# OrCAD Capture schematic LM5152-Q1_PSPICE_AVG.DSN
size Custom; title: LM5152-Q1 2.2-MHz Wide VIN Low-IQ Synchronous; rev: 1.0; note: Datasheet: NA     EVM: NA; note: Synchronous Step Down Converter
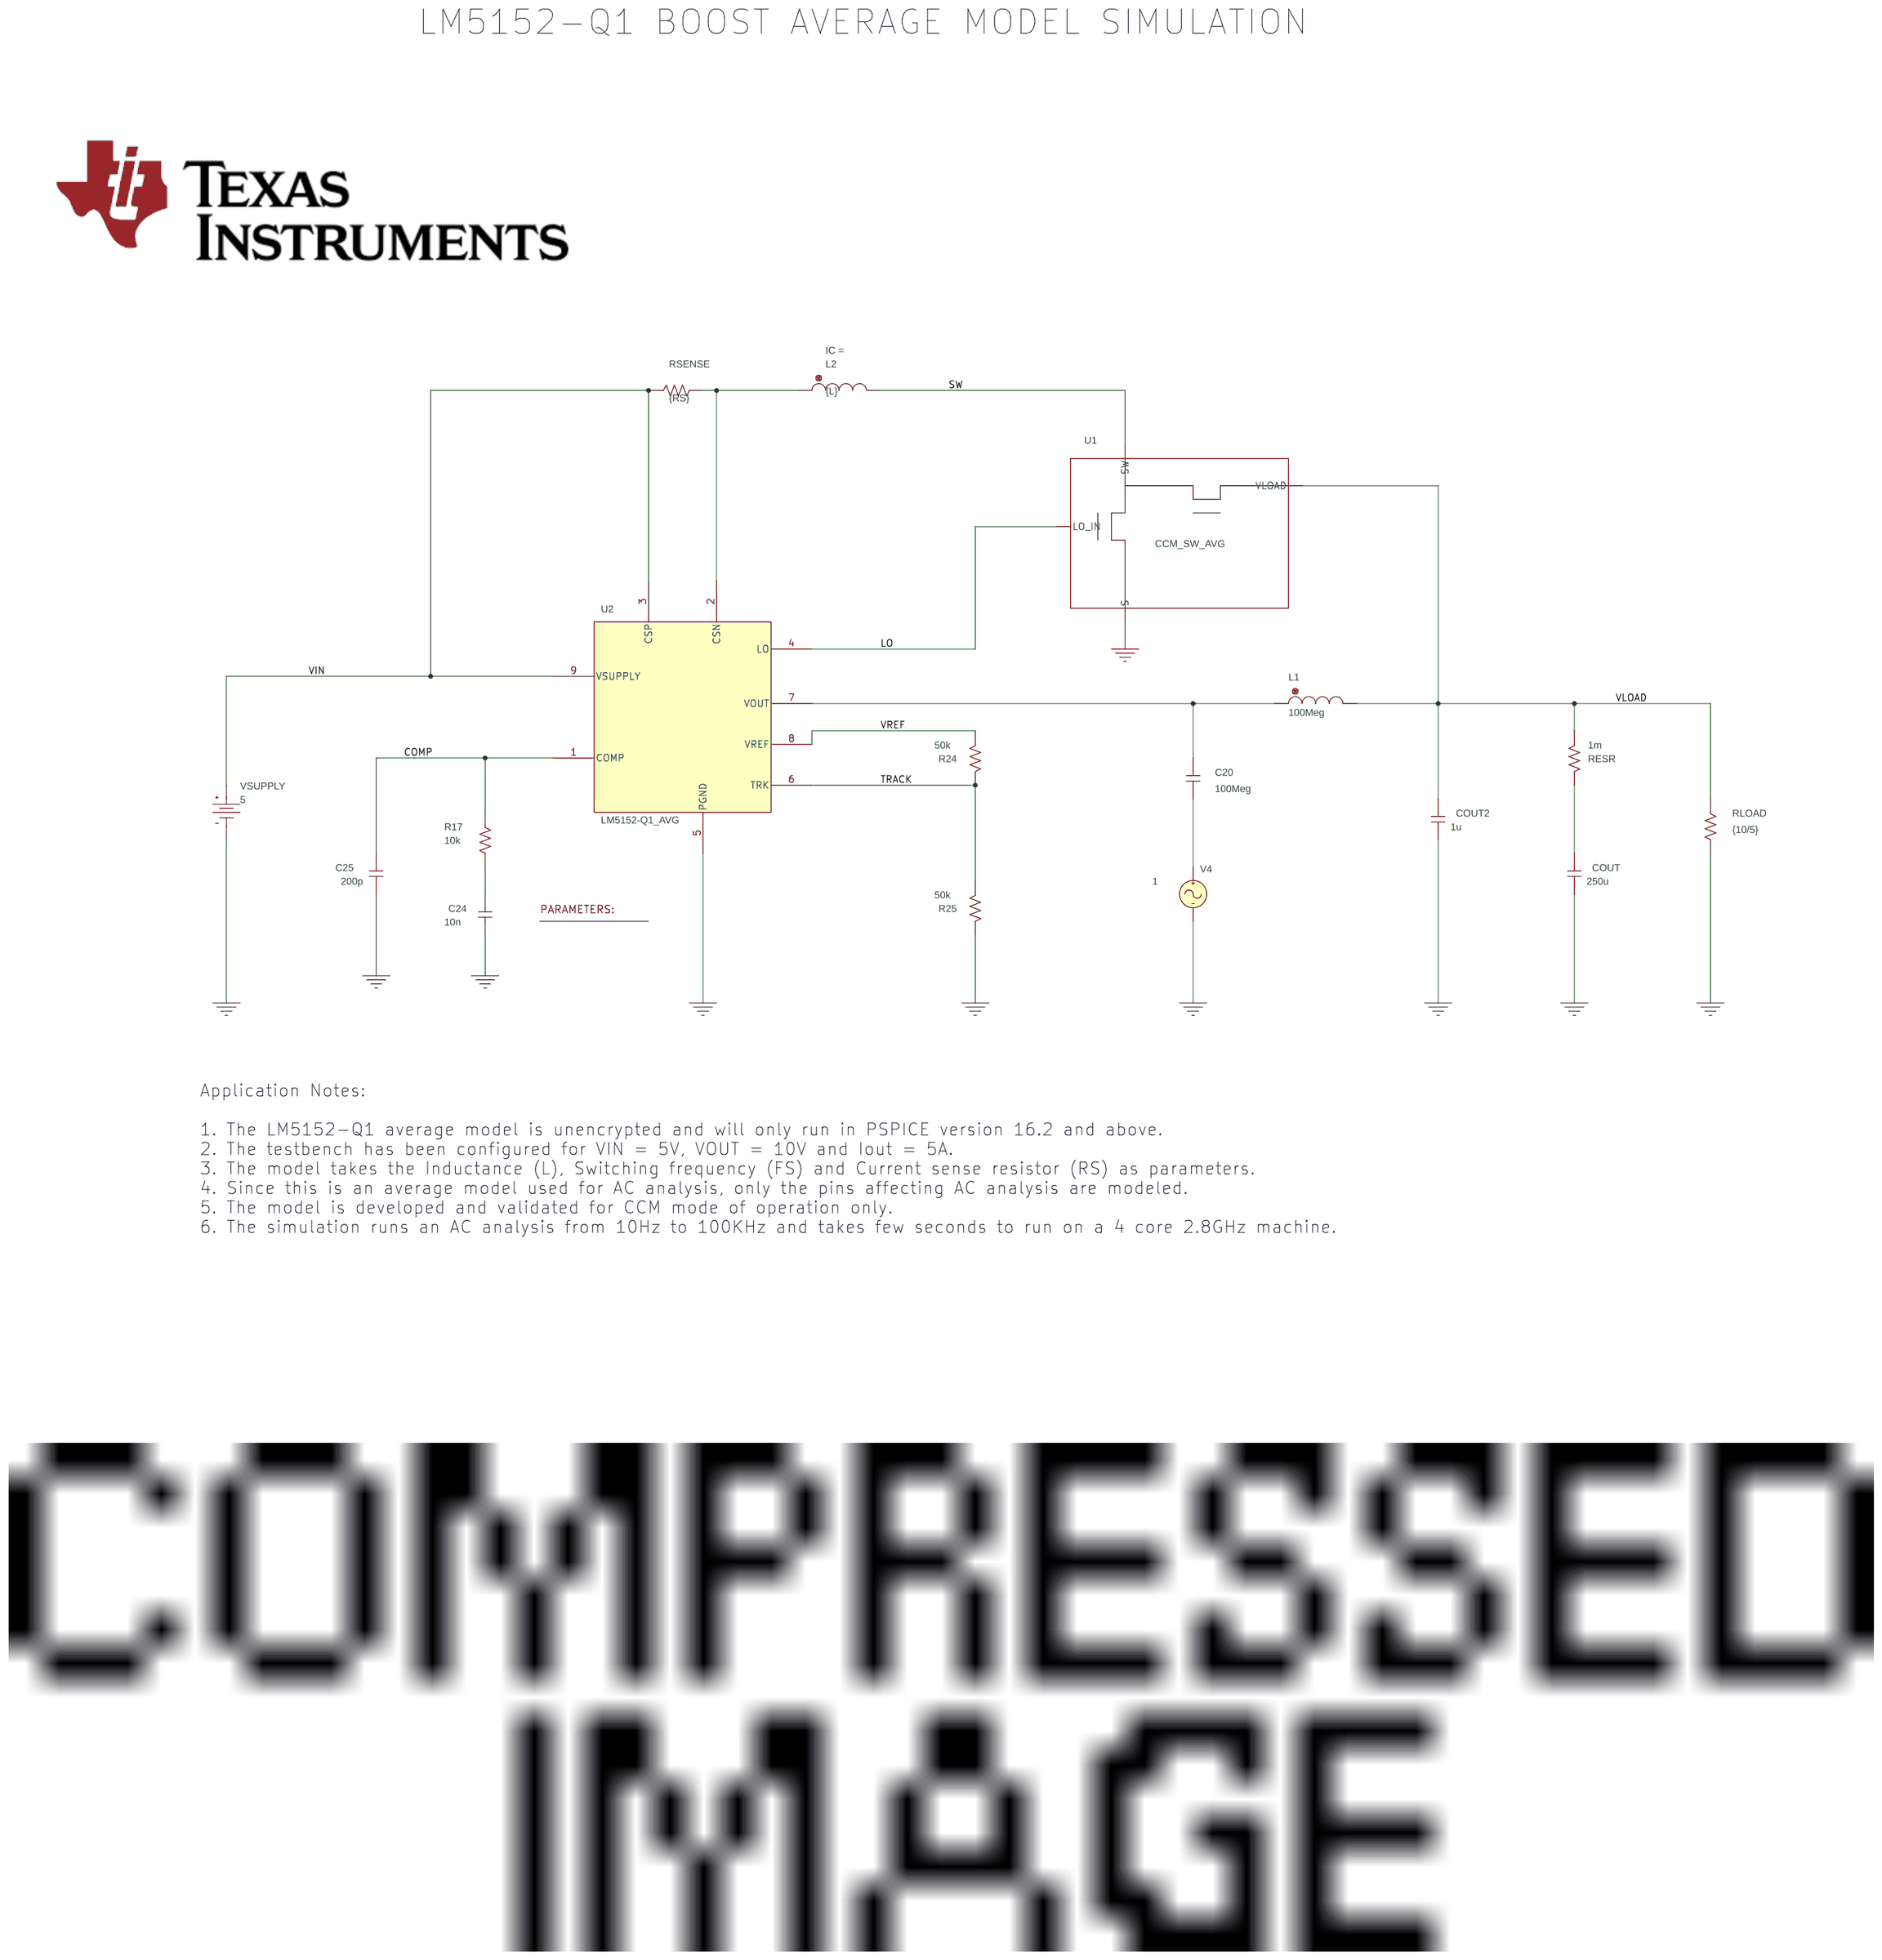
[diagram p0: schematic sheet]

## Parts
1  PARAM
C20  100Meg  [RAD/CK05]
C24  10n  [RAD/CK05]
C25  200p  [RAD/CK05]
COUT  250u  [RAD/CK05]
COUT2  1u  [RAD/CK05]
L1  100Meg  [DISC/.350x.175/LS.200x.100/.034]
L2  {L}  [DISC/.350x.175/LS.200x.100/.034]
R17  10k  [AX/RC05]
R24  50k  [AX/RC05]
R25  50k  [AX/RC05]
RESR  1m  [AX/RC05]
RLOAD  {10/5}  [AX/RC05]
RSENSE  {RS}  [AX/RC05]
U1  CCM_SW_AVG  [DRB0008A]
U2  LM5152-Q1_AVG
V4  VAC
VSUPPLY  VDC

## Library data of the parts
1 = PARAM: FS: 100k; L: 600n; RS: 2m; Vout_upper_range: 0
C20 C24 C25 COUT COUT2 = C
L1 L2 = L
R17 R24 R25 RESR RLOAD RSENSE = R
U1 = CCM_SW_AVG
U2 = LM5152-Q1_AVG
V4 = VAC: ACMAG: 1; ACPHASE: 0
VSUPPLY = VDC: DC: 5

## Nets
VIN: RSENSE.1 U2.3(CSP) U2.9(VSUPPLY) VSUPPLY.0(+)
0: C24.2 C25.2 COUT.2 COUT2.2 R25.2 RLOAD.2 U1.S U2.5(PGND) V4.2(-) VSUPPLY.1(-)
COMP: C25.1 R17.1 U2.1(COMP)
LO: U1.LO_IN U2.4(LO)
SW: L2.2 U1.SW
TRACK: R24.2 R25.1 U2.6(TRK)
VLOAD: COUT2.1 L1.2 RESR.1 RLOAD.1 U1.VLOAD
VREF: R24.1 U2.8(VREF)
N16777633: L2.1 RSENSE.2 U2.2(CSN)
N16777713: C20.1 L1.1 U2.7(VOUT)
N16777798: COUT.1 RESR.2
N16777801: C20.2 V4.1(+)
N16777883: C24.1 R17.2

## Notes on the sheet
- LM5152-Q1 BOOST AVERAGE MODEL SIMULATION
- Application Notes:
  1. The LM5152-Q1 average model is unencrypted and will only run in PSPICE version 16.2 and above.
  2. The testbench has been configured for VIN = 5V, VOUT = 10V and Iout = 5A.
  3. The model takes the Inductance (L), Switching frequency (FS) and Current sense resistor (RS) as parameters.
  4. Since this is an average model used for AC analysis, only the pins affecting AC analysis are modeled.
  5. The model is developed and validated for CCM mode of operation only.
  6. The simulation runs an AC analysis from 10Hz to 100KHz and takes few seconds to run on a 4 core 2.8GHz machine.
